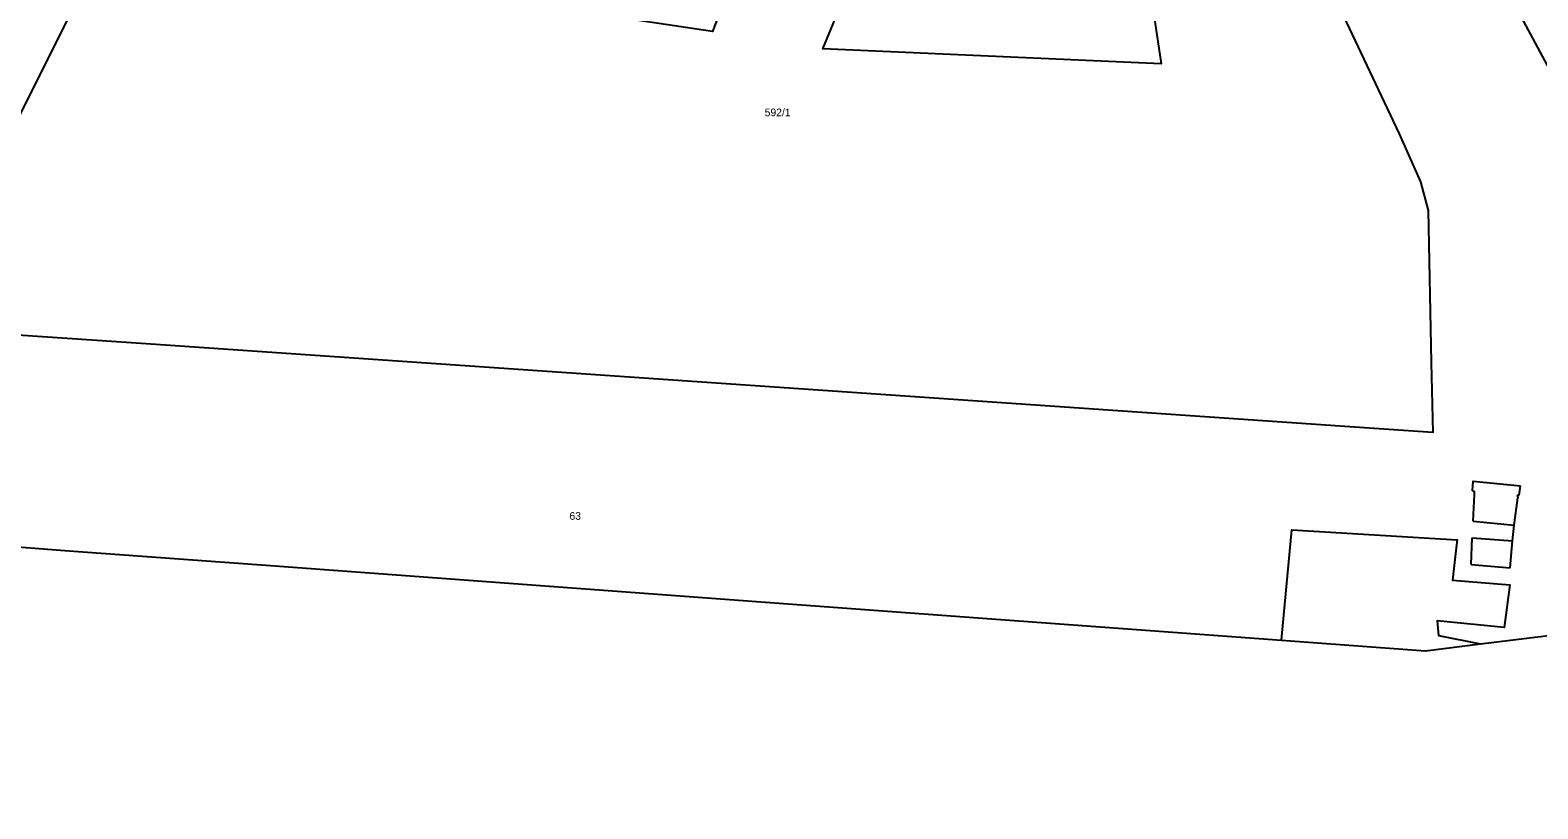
# Model space of a CAD drawing. Extents: x -882150 to -879379, y -1022570 to -1019819.
# Drawn here: x -880740.4 to -880409, y -1022569 to -1022397.8 of the extents above; entities that cross this region are included whole.
import ezdxf

# ---------------------------------------------------------------- set-up
doc = ezdxf.new("R2010")
doc.units = 0
for name, color, linetype in [('Hranice parcel', 7, 'Continuous'), ('Parcelní čísla', 7, 'Continuous'), ('Vnitřní kresba', 7, 'Continuous')]:
    doc.layers.add(name, color=color, linetype=linetype)

msp = doc.modelspace()

# ---------------------------------------------------------------- linework, layer by layer
at = {"layer": 'Hranice parcel'}
for points in [[(-880554.33, -1022173.06), (-880547.49, -1022197.27), (-880525.62, -1022257.49), (-880513.19, -1022293.42), (-880505.82, -1022316.63), (-880497.62, -1022366.49), (-880491.79, -1022405.22), (-880566.15, -1022401.94), (-880554.94, -1022374.73), (-880545.82, -1022364.54), (-880525.96, -1022352.62), (-880521.99, -1022325.21), (-880525.29, -1022297.87), (-880531.04, -1022289.54), (-880541.07, -1022285.64), (-880548.9, -1022286.02), (-880554.17, -1022295.26), (-880580.55, -1022371.99), (-880590.44, -1022398.07), (-880617.48, -1022394.1), (-880692.24, -1022388.39)], [(-880476.08, -1022337.43), (-880466.52, -1022356.43), (-880467.65, -1022358.04), (-880456.49, -1022386.58), (-880453.69, -1022390.45), (-880439.48, -1022420.61), (-880434.77, -1022431.18), (-880433.13, -1022437.44), (-880432.42, -1022470.88), (-880432.04, -1022486.25), (-880448.2, -1022485.14), (-880716.03, -1022466.72), (-880763.82, -1022463.43)], [(-880404.24, -1022530.56), (-880404.73, -1022508.83), (-880392.77, -1022456.11), (-880397.13, -1022423.7), (-880438.43, -1022346.79), (-880406.13, -1022376.33), (-880395.66, -1022384.1), (-880306.08, -1022468.64), (-880286.2, -1022489.18), (-880275.92, -1022500.64), (-880267.29, -1022514.55), (-880260.67, -1022530.6), (-880256.57, -1022546.88), (-880254.74, -1022558.34), (-880254.4, -1022569)], [(-880763.82, -1022463.43), (-880755, -1022441.07), (-880731.91, -1022394.96)], [(-880998.2, -1022517.1), (-880952.02, -1022516.52), (-880884.86, -1022515.58), (-880845.4, -1022512.28), (-880791.54, -1022507.64), (-880731.9, -1022512.26), (-880686.58, -1022515.6), (-880574.8, -1022523.88), (-880551.94, -1022525.52), (-880465.31, -1022531.94), (-880433.72, -1022534.28), (-880421.61, -1022532.75), (-880404.24, -1022530.56)]]:
    msp.add_lwpolyline(points, dxfattribs=at)
at = {"layer": 'Vnitřní kresba'}
for p, q in [((-880413.08, -1022500.05), (-880412.8, -1022497.95)), ((-880423.36, -1022499.08), (-880422.88, -1022499.14)), ((-880423.24, -1022505.78), (-880422.92, -1022499.86)), ((-880422.92, -1022499.86), (-880422.88, -1022499.14)), ((-880414.16, -1022506.64), (-880413.4, -1022500.59)), ((-880413.54, -1022500.01), (-880413.08, -1022500.05)), ((-880413.54, -1022500.01), (-880413.4, -1022500.59)), ((-880423.24, -1022505.78), (-880414.16, -1022506.64)), ((-880414.59, -1022510.04), (-880414.16, -1022506.64)), ((-880423.67, -1022515.25), (-880423.44, -1022509.44)), ((-880423.44, -1022509.44), (-880414.59, -1022510.04)), ((-880415.1, -1022515.98), (-880414.59, -1022510.04)), ((-880423.67, -1022515.25), (-880415.1, -1022515.98))]:
    msp.add_line(p, q, dxfattribs=at)
for points in [[(-880423.36, -1022499.08), (-880423.19, -1022496.98), (-880412.8, -1022497.95)], [(-880465.31, -1022531.94), (-880463.08, -1022507.63), (-880426.73, -1022509.83), (-880426.86, -1022510.94), (-880427.74, -1022518.69), (-880415.14, -1022519.73), (-880416.42, -1022529.16), (-880431.15, -1022527.68), (-880430.85, -1022530.86), (-880421.61, -1022532.75)]]:
    msp.add_lwpolyline(points, dxfattribs=at)

# ---------------------------------------------------------------- texts
at = {"layer": 'Parcelní čísla'}
for s, p in [('592/1', (-880578.96, -1022416.73)), ('63', (-880621.881, -1022505.45))]:
    msp.add_text(s, height=1.7, dxfattribs=at).set_placement(p)

doc.saveas('drawing.dxf')
